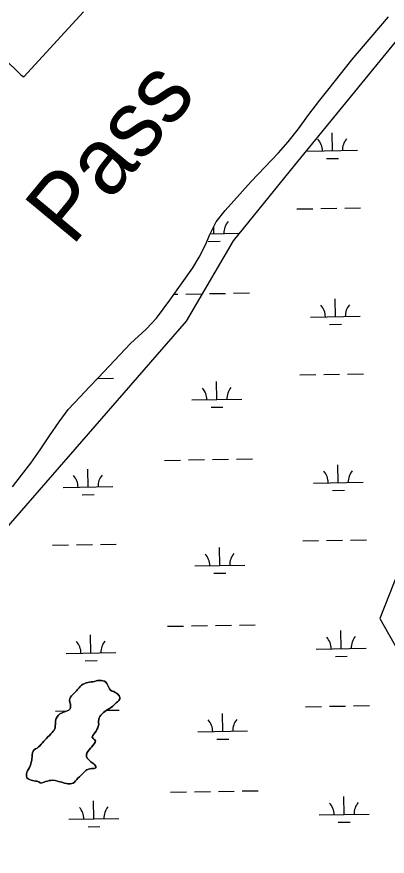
# Model space of a CAD drawing. Extents: x 3903937 to 3942190, y 260677 to 286651.
# Drawn here: x 3911870 to 3912613, y 279196 to 280879 of the extents above; entities that cross this region are included whole.
import ezdxf

# ---------------------------------------------------------------- set-up
doc = ezdxf.new("R2010")
doc.units = 0
for name, color, linetype in [('V-RIVR-IDEN', 7, 'Continuous'), ('V-SITE-VEGE', 7, 'Continuous'), ('V-TOPO-SHOR', 7, 'Continuous'), ('V-WETL-SWMP', 7, 'Continuous')]:
    doc.layers.add(name, color=color, linetype=linetype)

msp = doc.modelspace()

# ---------------------------------------------------------------- linework, layer by layer
at = {"layer": 'V-SITE-VEGE'}
for points in [[(3911255, 278745.3), (3911368.5, 279048.1), (3911633.3, 279606.4), (3912210.2, 280268.7), (3912304.8, 280429.5), (3912427.7, 280580.9), (3912683.1, 280893.2)], [(3912635.8, 279767.2), (3912598, 279672.6), (3912635.8, 279606.4)]]:
    msp.add_lwpolyline(points, dxfattribs=at)
at = {"layer": 'V-TOPO-SHOR'}
for points in [[(3911653.3, 280985.5), (3911770.3, 280867.3), (3911878.8, 280761.8), (3911884.5, 280758.4), (3912003.7, 280888.3)], [(3911861.6, 279936.4), (3911879.6, 279959.7), (3911898.5, 279984), (3911917.1, 280010.7), (3911935.4, 280038.3), (3911954.8, 280066.7), (3911973, 280091.1), (3911997, 280117), (3912015.8, 280136.9), (3912033.6, 280155.6), (3912098, 280223.8), (3912129.3, 280252.3), (3912150.2, 280274.3), (3912176.7, 280310.7), (3912201.8, 280345.3), (3912223.4, 280375.6), (3912235.8, 280396.6), (3912249.3, 280422.5), (3912256.2, 280440.5), (3912270.2, 280467.7), (3912288.2, 280490.2), (3912340.2, 280548.1), (3912367.8, 280577.1), (3912394.6, 280605.7), (3912414.4, 280627.9), (3912435.2, 280653.7), (3912453.8, 280679.9), (3912477.9, 280711.2), (3912496.6, 280734.9), (3912519.2, 280763.8), (3912542, 280792), (3912615.4, 280878.2)], [(3911916.9, 279343.1), (3911914.3, 279345.1), (3911911.1, 279346), (3911908, 279346.4), (3911905, 279346.8), (3911901.7, 279347.6), (3911898.7, 279348.3), (3911895.7, 279349.5), (3911892.8, 279350.9), (3911890.5, 279353), (3911889.3, 279356.7), (3911889.4, 279360.6), (3911890.2, 279364.3), (3911891.4, 279367.2), (3911893.4, 279370.3), (3911895.5, 279374), (3911897.1, 279377.2), (3911898.1, 279380.4), (3911899.2, 279384.4), (3911899.9, 279388.2), (3911900.4, 279391.3), (3911900.7, 279395.1), (3911901, 279399.1), (3911901.8, 279403.1), (3911903, 279406.4), (3911905, 279409.1), (3911907.6, 279410.8), (3911910.7, 279412.4), (3911913.8, 279414.8), (3911916.4, 279417.3), (3911919, 279420.4), (3911921.5, 279423.4), (3911924.1, 279426.5), (3911926.7, 279429.1), (3911929.4, 279432), (3911931.9, 279434.4), (3911935.9, 279438.1), (3911938.5, 279441.1), (3911940.8, 279443.7), (3911943, 279446.2), (3911945, 279448.8), (3911946.7, 279453), (3911947.1, 279456.3), (3911947.5, 279461), (3911947.6, 279464.2), (3911947.9, 279467.4), (3911949.2, 279472), (3911950.8, 279475.2), (3911953.7, 279478.7), (3911956.7, 279481.4), (3911960.8, 279483.3), (3911963.8, 279484.3), (3911967.9, 279485.7), (3911971.3, 279487.3), (3911974.2, 279488.7), (3911976.5, 279490.7), (3911977.9, 279493.4), (3911977.9, 279497), (3911977.6, 279500.8), (3911976.7, 279504.7), (3911975.9, 279507.9), (3911976.2, 279511.7), (3911977.7, 279514.6), (3911980, 279517.3), (3911982.1, 279519.5), (3911984.9, 279522.5), (3911987.2, 279524.8), (3911989.9, 279527.4), (3911992.1, 279530), (3911994.9, 279533.4), (3911997.1, 279536.1), (3911999.6, 279538.5), (3912003.4, 279540.7), (3912006.2, 279542.1), (3912009.2, 279543.1), (3912012.2, 279543.8), (3912016.1, 279544.6), (3912019.2, 279545.1), (3912022.4, 279545.6), (3912025.7, 279546.3), (3912029, 279547.2), (3912032.1, 279548), (3912035.4, 279548.4), (3912039.6, 279547.9), (3912042.7, 279547.4), (3912046.2, 279546.5), (3912048.9, 279544.8), (3912050.7, 279542.3), (3912052.9, 279538.2), (3912054.1, 279535.4), (3912056, 279531.5), (3912058.3, 279528.9), (3912061.3, 279526.9), (3912064.5, 279525.7), (3912067.1, 279524), (3912070, 279522.8), (3912073, 279520.6), (3912075.2, 279517.6), (3912076.8, 279514.4), (3912077, 279511), (3912075, 279507.9)], [(3912075, 279507.9), (3912072.2, 279505.5), (3912069.6, 279503.5), (3912067.1, 279501.2), (3912065, 279498.8), (3912062.4, 279496.4), (3912059.9, 279494.4), (3912056, 279491.7), (3912052.8, 279489.9), (3912049.4, 279488), (3912046.6, 279486.1), (3912043.7, 279483.7), (3912041, 279481.2), (3912038.6, 279478.4), (3912036.8, 279475.9), (3912035.3, 279473.3), (3912034.4, 279470.1), (3912034, 279466.8), (3912034.2, 279463.2), (3912034.3, 279460.1), (3912033.4, 279456.3), (3912032.3, 279453), (3912030.8, 279450.1), (3912029, 279446.5), (3912026.6, 279443), (3912024.5, 279440.7), (3912022.6, 279438.1), (3912021.2, 279434.6), (3912023.2, 279431.9), (3912025.5, 279429.9), (3912027.7, 279427.6), (3912027.5, 279424.2), (3912025.4, 279420.8), (3912022.8, 279417.5), (3912020, 279414.6), (3912017.7, 279412.3), (3912015.4, 279409.4), (3912012.6, 279405.7), (3912010.5, 279402.2), (3912009.8, 279399.3), (3912010, 279395.8), (3912011.4, 279392.7), (3912013.3, 279390.1), (3912016.3, 279386.7), (3912018.8, 279384.7), (3912021.3, 279382.8), (3912024.4, 279380.7), (3912026.8, 279378.7), (3912028.7, 279376), (3912028.6, 279372.9), (3912025.1, 279371.4), (3912020.8, 279371.7), (3912017.4, 279371.3), (3912013.9, 279370.6), (3912010.8, 279369.3), (3912008.3, 279367.6), (3912005.7, 279365.2), (3912002.9, 279362.4), (3912000.6, 279359.8), (3911997.9, 279357.2), (3911995.5, 279354.8), (3911992.7, 279352), (3911990.2, 279349.8), (3911988.1, 279346.7), (3911985.9, 279344), (3911983.3, 279342.3), (3911980.3, 279341.5), (3911977.1, 279340.8), (3911972.5, 279340.7), (3911969.5, 279341.4), (3911965.5, 279342.5), (3911960.2, 279344), (3911956.2, 279345.2), (3911951.4, 279346.4), (3911946.7, 279347.4), (3911941.4, 279348.1), (3911938.2, 279347.9), (3911935, 279347.5), (3911931.5, 279346.6), (3911927.9, 279345.6), (3911925, 279344.5), (3911922.2, 279343.5), (3911919.1, 279342.5), (3911916.9, 279343.1)]]:
    msp.add_lwpolyline(points, dxfattribs=at)
at = {"layer": 'V-WETL-SWMP'}
for p, q in [((3912503.1, 280610), (3912502.4, 280646)), ((3912453.1, 280609.1), (3912553.1, 280610.9)), ((3912491.3, 280594.3), (3912515.3, 280594.8)), ((3912431.7, 280493.3), (3912463.7, 280493.8)), ((3912479.7, 280494.1), (3912511.7, 280494.7)), ((3912527.7, 280495), (3912559.7, 280495.5)), ((3912265.5, 280443.9), (3912265.2, 280458)), ((3912257.9, 280443.8), (3912315.5, 280444.8)), ((3912253.8, 280428.3), (3912277.7, 280428.7)), ((3912185.2, 280322.4), (3912192.8, 280322.5)), ((3912208.8, 280322.8), (3912240.8, 280323.4)), ((3912256.7, 280323.7), (3912288.7, 280324.2)), ((3912304.7, 280324.5), (3912336.7, 280325.1)), ((3912508.9, 280277.4), (3912508.3, 280313.4)), ((3912458.9, 280276.5), (3912558.9, 280278.2)), ((3912497.2, 280261.7), (3912521.2, 280262.1)), ((3912031.7, 280153.5), (3912063.7, 280154.1)), ((3912437.6, 280160.7), (3912469.5, 280161.2)), ((3912485.5, 280161.5), (3912517.5, 280162.1)), ((3912533.5, 280162.3), (3912565.5, 280162.9)), ((3912271.3, 280111.3), (3912270.7, 280147.3)), ((3912221.3, 280110.4), (3912321.3, 280112.2)), ((3912259.6, 280095.7), (3912283.6, 280096.1)), ((3912166.6, 279989.4), (3912198.6, 279989.9)), ((3912214.6, 279990.2), (3912246.6, 279990.8)), ((3912262.6, 279991), (3912294.6, 279991.6)), ((3912310.6, 279991.9), (3912342.6, 279992.5)), ((3912012.9, 279935.9), (3912012.3, 279971.9)), ((3912514.8, 279944.7), (3912514.1, 279980.7)), ((3911963, 279935), (3912062.9, 279936.8)), ((3912464.8, 279943.9), (3912564.8, 279945.6)), ((3912001.2, 279920.3), (3912025.2, 279920.7)), ((3912503, 279929.1), (3912527, 279929.5)), ((3911941.6, 279819.2), (3911973.6, 279819.8)), ((3911989.6, 279820), (3912021.6, 279820.6)), ((3912037.6, 279820.9), (3912069.6, 279821.5)), ((3912277.2, 279778.7), (3912276.6, 279814.7)), ((3912443.4, 279828), (3912475.4, 279828.6)), ((3912491.4, 279828.9), (3912523.4, 279829.4)), ((3912539.4, 279829.7), (3912571.4, 279830.3)), ((3912227.2, 279777.8), (3912327.2, 279779.5)), ((3912265.5, 279763), (3912289.5, 279763.5)), ((3912172.5, 279656.7), (3912204.5, 279657.3)), ((3912220.5, 279657.6), (3912252.5, 279658.1)), ((3912268.5, 279658.4), (3912300.5, 279659)), ((3912316.5, 279659.3), (3912348.4, 279659.8)), ((3912520.6, 279612.1), (3912520, 279648.1)), ((3912018.8, 279603.3), (3912018.2, 279639.3)), ((3912470.6, 279611.2), (3912570.6, 279613)), ((3911968.8, 279602.4), (3912068.8, 279604.2)), ((3912508.9, 279596.5), (3912532.9, 279596.9)), ((3912007.1, 279587.6), (3912031.1, 279588.1)), ((3912449.3, 279495.4), (3912481.3, 279496)), ((3912497.3, 279496.3), (3912529.3, 279496.8)), ((3912545.2, 279497.1), (3912577.2, 279497.7)), ((3911947.4, 279486.6), (3911970.6, 279487)), ((3912050, 279488.4), (3912075.4, 279488.8)), ((3912283, 279446), (3912282.4, 279482)), ((3912233, 279445.2), (3912333, 279446.9)), ((3912271.3, 279430.4), (3912295.3, 279430.8)), ((3912226.3, 279325), (3912258.3, 279325.5)), ((3912274.3, 279325.8), (3912306.3, 279326.4)), ((3912322.3, 279326.6), (3912354.3, 279327.2)), ((3912178.3, 279324.1), (3912210.3, 279324.7)), ((3912526.5, 279279.5), (3912525.8, 279315.5)), ((3912024.7, 279270.7), (3912024, 279306.7)), ((3912476.5, 279278.6), (3912576.5, 279280.4)), ((3911974.7, 279269.8), (3912074.6, 279271.5)), ((3912514.8, 279263.9), (3912538.8, 279264.3)), ((3912012.9, 279255), (3912036.9, 279255.4))]:
    msp.add_line(p, q, dxfattribs=at)
for points in [[(3911861.6, 279936.4), (3911879.6, 279959.7), (3911898.5, 279984), (3911917.1, 280010.7), (3911935.4, 280038.3), (3911954.9, 280066.7), (3911973, 280091.1), (3911997, 280117), (3912015.8, 280136.9), (3912033.6, 280155.6), (3912098, 280223.8), (3912129.3, 280252.3), (3912150.2, 280274.3), (3912176.7, 280310.7), (3912201.8, 280345.3), (3912223.4, 280375.6), (3912235.8, 280396.6), (3912249.3, 280422.5), (3912256.2, 280440.5), (3912270.2, 280467.7), (3912288.2, 280490.2), (3912340.2, 280548.1), (3912367.8, 280577.1), (3912394.6, 280605.7), (3912414.4, 280627.9), (3912435.2, 280653.7), (3912453.8, 280679.9), (3912477.9, 280711.2), (3912496.6, 280734.9), (3912519.2, 280763.8), (3912542, 280792), (3912615.4, 280878.2)], [(3912035.4, 279548.4), (3912032.1, 279548), (3912029, 279547.2), (3912025.7, 279546.3), (3912022.4, 279545.6), (3912019.2, 279545.1), (3912016.2, 279544.6), (3912012.2, 279543.8), (3912009.2, 279543.1), (3912006.2, 279542.1), (3912003.4, 279540.7), (3911999.6, 279538.5), (3911997.1, 279536.1), (3911994.9, 279533.4), (3911992.1, 279530), (3911989.9, 279527.4), (3911987.2, 279524.8), (3911984.9, 279522.5), (3911982.1, 279519.5), (3911980, 279517.3), (3911977.7, 279514.6), (3911976.2, 279511.7), (3911975.9, 279507.9), (3911976.7, 279504.7), (3911977.6, 279500.8), (3911977.9, 279497), (3911977.9, 279493.4), (3911976.5, 279490.7), (3911974.2, 279488.7), (3911971.3, 279487.3), (3911967.9, 279485.7), (3911963.8, 279484.3), (3911960.8, 279483.3), (3911956.7, 279481.4), (3911953.7, 279478.7), (3911950.8, 279475.2), (3911949.2, 279472), (3911947.9, 279467.4), (3911947.6, 279464.2), (3911947.5, 279461), (3911947.1, 279456.3), (3911946.7, 279453), (3911945, 279448.8), (3911943, 279446.2), (3911940.8, 279443.7), (3911938.5, 279441.1), (3911935.9, 279438.1), (3911931.9, 279434.4), (3911929.4, 279432), (3911926.7, 279429.1), (3911924.1, 279426.5), (3911921.5, 279423.4), (3911919, 279420.4), (3911916.4, 279417.3), (3911913.8, 279414.8), (3911910.7, 279412.4), (3911907.6, 279410.8), (3911905, 279409.1), (3911903, 279406.4), (3911901.8, 279403.1), (3911901, 279399.1), (3911900.7, 279395.1), (3911900.4, 279391.3), (3911899.9, 279388.2), (3911899.2, 279384.4), (3911898.1, 279380.4), (3911897.1, 279377.2), (3911895.5, 279374), (3911893.4, 279370.3), (3911891.4, 279367.2), (3911890.2, 279364.3), (3911889.4, 279360.6), (3911889.3, 279356.7), (3911890.5, 279353), (3911892.8, 279350.9), (3911895.7, 279349.5), (3911898.7, 279348.3), (3911901.7, 279347.6), (3911905, 279346.8), (3911908, 279346.4), (3911911.1, 279346), (3911914.3, 279345.1), (3911916.9, 279343.1), (3911919.1, 279342.5)], [(3911919.1, 279342.5), (3911922.2, 279343.5), (3911925, 279344.5), (3911927.9, 279345.6), (3911931.5, 279346.6), (3911935, 279347.5), (3911938.2, 279347.9), (3911941.4, 279348.1), (3911946.7, 279347.4), (3911951.4, 279346.4), (3911956.2, 279345.2), (3911960.2, 279344), (3911965.5, 279342.5), (3911969.5, 279341.4), (3911972.5, 279340.7), (3911977.1, 279340.8), (3911980.3, 279341.5), (3911983.3, 279342.3), (3911985.9, 279344), (3911988.1, 279346.7), (3911990.2, 279349.8), (3911992.7, 279352), (3911995.5, 279354.8), (3911997.9, 279357.2), (3912000.6, 279359.8), (3912002.9, 279362.4), (3912005.7, 279365.2), (3912008.3, 279367.6), (3912010.8, 279369.3), (3912013.9, 279370.6), (3912017.4, 279371.3), (3912020.8, 279371.7), (3912025.1, 279371.4), (3912028.6, 279372.9), (3912028.7, 279376), (3912026.8, 279378.7), (3912024.4, 279380.7), (3912021.3, 279382.8), (3912018.8, 279384.7), (3912016.3, 279386.7), (3912013.3, 279390.1), (3912011.4, 279392.7), (3912010, 279395.8), (3912009.8, 279399.3), (3912010.5, 279402.2), (3912012.6, 279405.7), (3912015.4, 279409.4), (3912017.7, 279412.3), (3912020, 279414.6), (3912022.8, 279417.5), (3912025.4, 279420.8), (3912027.5, 279424.2), (3912027.7, 279427.6), (3912025.5, 279429.9), (3912023.2, 279431.9), (3912021.2, 279434.6), (3912022.6, 279438.1), (3912024.5, 279440.7), (3912026.6, 279443), (3912029, 279446.5), (3912030.8, 279450.1), (3912032.3, 279453), (3912033.4, 279456.3), (3912034.3, 279460.1), (3912034.2, 279463.2), (3912034, 279466.8), (3912034.4, 279470.1), (3912035.3, 279473.3), (3912036.8, 279475.9), (3912038.6, 279478.4), (3912041, 279481.2), (3912043.7, 279483.7), (3912046.6, 279486.1), (3912049.4, 279488), (3912052.8, 279489.9), (3912056, 279491.7), (3912059.9, 279494.4), (3912062.4, 279496.4), (3912065, 279498.8), (3912067.1, 279501.2), (3912069.6, 279503.5), (3912072.2, 279505.5), (3912075, 279507.9), (3912077, 279511), (3912076.8, 279514.4), (3912075.2, 279517.6), (3912073, 279520.6), (3912070, 279522.8), (3912067.1, 279524), (3912064.5, 279525.7), (3912061.3, 279526.9), (3912058.3, 279528.9), (3912056, 279531.5), (3912054.1, 279535.4), (3912052.9, 279538.2), (3912050.7, 279542.3), (3912048.9, 279544.8), (3912046.2, 279546.5), (3912042.7, 279547.4), (3912039.6, 279547.9), (3912035.4, 279548.4)]]:
    msp.add_lwpolyline(points, dxfattribs=at)
for centre, start, end in [((3912447.8, 280609.5), 0.2366, 41.7802), ((3912558.3, 280611.4), 140.2366, 181.7802), ((3912320.7, 280445.4), 140.2366, 181.7802), ((3912453.7, 280276.9), 0.2366, 41.7802), ((3912564.1, 280278.8), 140.2366, 181.7802), ((3912216.1, 280110.8), 0.2366, 41.7802), ((3912326.6, 280112.7), 140.2366, 181.7802), ((3912459.5, 279944.2), 0.2366, 41.7802), ((3912570, 279946.2), 140.2366, 181.7802), ((3911957.7, 279935.4), 0.2366, 41.7802), ((3912068.2, 279937.4), 140.2366, 181.7802), ((3912221.9, 279778.2), 0.2366, 41.7802), ((3912332.4, 279780.1), 140.2366, 181.7802), ((3912465.4, 279611.6), 0.2366, 41.7802), ((3912575.9, 279613.6), 140.2366, 181.7802), ((3911963.6, 279602.8), 0.2366, 41.7802), ((3912074, 279604.7), 140.2366, 181.7802), ((3912227.8, 279445.5), 0.2366, 41.7802), ((3912338.3, 279447.5), 140.2366, 181.7802), ((3911969.4, 279270.2), 0.2366, 41.7802), ((3912079.9, 279272.1), 140.2366, 181.7802), ((3912471.2, 279279), 0.2366, 41.7802), ((3912581.7, 279280.9), 140.2366, 181.7802)]:
    msp.add_arc(centre, 35.2, start, end, dxfattribs=at)

# ---------------------------------------------------------------- texts
at = {"layer": 'V-RIVR-IDEN'}
msp.add_text('Pass', height=133, rotation=50.3344, dxfattribs=at).set_placement((3911980.7, 280416.6))

doc.saveas('drawing.dxf')
